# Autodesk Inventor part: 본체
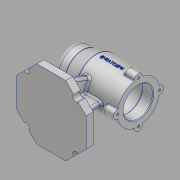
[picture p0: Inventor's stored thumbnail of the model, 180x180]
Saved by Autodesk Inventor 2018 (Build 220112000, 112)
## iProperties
Created: 2021-01
Part Number: 본체
Material: 알루미늄 6061
Document SubType Name: Modeling
Designer: home
Density: 2.7 g/cm^3
Appearance: 알루미늄 - 평지
Mass: 630.142 g
Surface Area: 614.537 cm^2
Volume: 233.386 cm^3
Author: home
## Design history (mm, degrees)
sketch "스케치1"
  geometry: L1 (20.711, -50)-(-20.711, -50); L2 (-20.711, -50)-(-50, -20.711); L3 (-50, -20.711)-(-50, 20.711); L4 (-50, 20.711)-(-20.711, 50); L5 (-20.711, 50)-(20.711, 50); L6 (20.711, 50)-(50, 20.711); L7 (50, 20.711)-(50, -20.711); L8 (50, -20.711)-(20.711, -50); C1 r 50 at (0, 0); 2 further points
  constraints: 16 end point, 2 coincident, 1 centre point, 1 horizontal alignment, 1 tangent, 17 other
  dimensions: "d0" = 100 diameter of C1
extrude "돌출1" new body sketch "스케치1" distance "d1" = 10; taper "d2" = 0 deg
sketch "스케치2" dims "d3" = 100
  geometry: L1 (0, 0)-(50, 0); L2 (50, 20.711)-(20.711, 50) reference; C1 r 4.5 at (35.355, 35.355); 1 further point
  constraints: 2 end point, 1 centre point, 1 coincident, 1 horizontal, 1 horizontal alignment, 1 midpoint, 2 other
  dimensions: "d4" = 9 diameter of C1
extrude "돌출2" cut sketch "스케치2" distance "d5" = 10; taper "d6" = 0 deg
sketch "스케치3"
  geometry: L1 (50, 75)-(-50, 75); L2 (-50, 75)-(-50, 100); L3 (-50, 100)-(-30, 100); L4 (-30, 100)-(-10, 105); L5 (-10, 105)-(50, 105); L6 (50, 105)-(50, 96); L7 (-44, 75)-(-44, 85.5); L8 (-44, 85.5)-(-41, 85.5); L9 (-41, 85.5)-(-41, 91); L10 (-41, 91)-(-37, 91); L11 (-37, 91)-(-37, 92.5); L12 (-37, 92.5)-(-19, 92.5); L13 (-19, 92.5)-(-19, 96); L14 (-19, 96)-(-7, 96); L15 (-7, 96)-(-7, 99); L16 (-7, 99)-(35, 99); L17 (35, 99)-(35, 96); L18 (35, 96)-(50, 96); 1 further point
  constraints: 36 end point, 12 perpendicular, 2 point on line, 2 vertical, 1 horizontal, 1 horizontal alignment, 1 parallel, 1 vertical alignment
  dimensions: "d10" = 100 distance of L1.start L1.end; "d11" = 75 vertical distance of point (0, 0) L1.start; "d12" = 50 horizontal distance of point (0, 0) L1.start; "d13" = 60 diameter of L5 L1; "d14" = 50 diameter of L3 L1; "d15" = 20 distance of L3.end L2.end; "d16" = 40 horizontal distance of L4.end L2.end; "d17" = 3 distance between parallel lines of L9 L7; "d18" = 4 distance between parallel lines of L11 L9; "d19" = 18 distance between parallel lines of L13 L11; "d20" = 12 distance between parallel lines of L15 L13; "d21" = 42 distance between parallel lines of L17 L15; "d22" = 15 distance of L17.end L6.end; "d23" = 21 diameter of L8 L1; "d24" = 32 diameter of L10 L1; "d25" = 35 diameter of L12 L1; "d26" = 42 diameter of L14 L1; "d27" = 48 diameter of L16 L1
revolve "회전1" sketch "스케치3" stored, may be unused: angle "d28" = 90 deg
fillet "모깎기1" dims "d29" = 10, "d30" = 3, "d31" = 0.3
sketch "스케치4"
  geometry: L1 (-27, -4)-(27, -4); L2 (27, -4)-(27, 4); L3 (27, 4)-(-27, 4); L4 (-27, 4)-(-27, -4); L5 (-27, -4)-(27, 4); L6 (27, -4)-(-27, 4); L7 (50, 20.711)-(50, -20.711) reference; 1 further point
  constraints: 12 end point, 2 midpoint, 2 parallel, 1 horizontal, 1 perpendicular
  dimensions: "d32" = 23 distance between parallel lines of L7 L2; "d33" = 8 distance of L3.end L1.start
extrude "돌출3" join sketch "스케치4" stored distance "d34" = 10; taper "d35" = 0 deg
feature "면 기울기1" dims angle "d36" = 11 deg
sketch "스케치5"
  geometry: L1 (10, 38.537)-(10, 30.855) reference; L2 (10, 35)-(52.786, 19.427); L3 (0, 50)-(10, 50) reference; 1 further point
  constraints: 2 end point, 1 point on line
  dimensions: "d37" = 15 distance from line of L2.start L3; "d38" = 110 deg angle of L1 L2
feature "리브1" sketch "스케치5" dims "d39" = 1, "d40" = 8, "d41" = 0, "d42" = 0, "d43" = 1, "d44" = 1
sketch "스케치6"
  geometry: A1 r 6 centre (0, 30) between (5.97, 29.4) and (-5.97, 29.4); A2 r 30 centre (0, 0) between (0, 30) and (-5.97, 29.4) reference; A3 r 30 centre (0, 0) between (5.97, 29.4) and (-5.97, 29.4); 1 further point
  constraints: 8 point on circle, 2 centre point, 1 coincident, 1 vertical alignment
  dimensions: "d45" = 6 radius of A1
extrude "돌출4" join sketch "스케치6" distance "d46" = 16; taper "d47" = 0 deg
sketch "스케치7"
  geometry: A1 r 6 centre (0, 0) between (5.97, -0.6) and (-5.97, -0.6) reference; 2 further points
  constraints: 1 coincident
hole "구멍1" sketch "스케치7" at (0, 0) diameter "d48" = 3.242; stored, may be unused: countersink angle "d52" = 90 deg, drill point angle "d54" = 118 deg; dims "d49" = 8, "d50" = 4, "d51" = 2, "d53" = 10
fillet "모깎기2" dims "d55" = 3
fillet "모깎기3" dims "d56" = 1
fillet "모깎기4" dims "d60" = 3
fillet "모깎기5" dims "d61" = 3
node "작업 평면1"
sketch "스케치8"
  geometry: L1 (50, 81.771)-(50, 104.226) reference; 2 further points
  constraints: 1 other
  dimensions: "d63" = 38 distance from line of L1 point (12, 75); "d64" = 75 vertical distance of point (0, 0) point (12, 75)
feature "엠보싱1" sketch "스케치8" dims "d0" = 100, "d65" = 0.5, "d66" = 0
chamfer "모따기1" distance "d67" = 1; stored, may be unused: second distance "d68" = 2, angle "d69" = 45 deg
node "솔리드1"
pattern_circular "원형 패턴1" dims angle "d8" = 360 deg
mirror "미러1"
pattern_circular "원형 패턴2" dims "d58" = 360 deg
